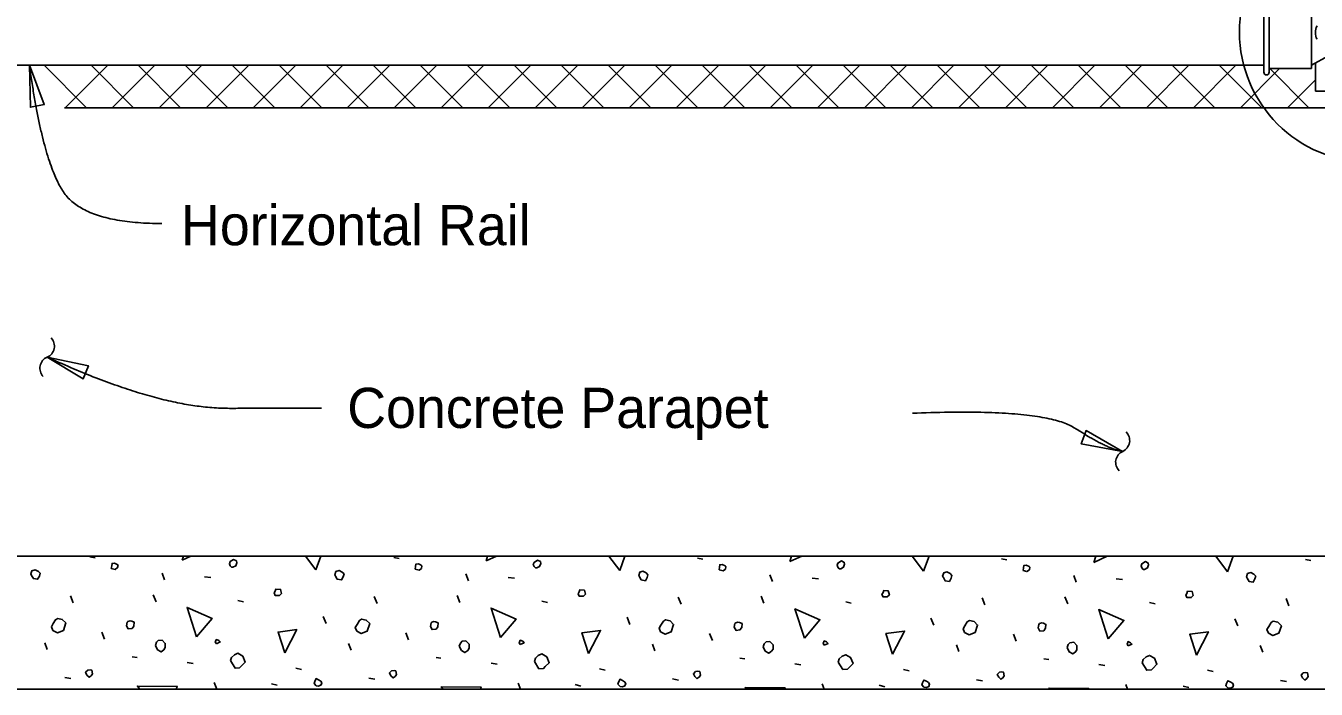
# Model space of a CAD drawing. Extents: x 0 to 41.1, y 0 to 25.9.
# Drawn here: x 5.34 to 11.81, y 14.04 to 17.37 of the extents above; entities that cross this region are included whole.
import ezdxf

# ---------------------------------------------------------------- set-up
doc = ezdxf.new("R2010")
doc.units = 0
for name, color, linetype in [('Dimension', 7, 'Continuous'), ('Miscellaneous', 7, 'Continuous'), ('SteelMisc', 7, 'Continuous'), ('SupstrConc', 7, 'Continuous'), ('TextStructures', 7, 'Continuous')]:
    doc.layers.add(name, color=color, linetype=linetype)

msp = doc.modelspace()

# ---------------------------------------------------------------- linework, layer by layer
at = {"layer": 'Dimension'}
for points in [[(5.3566, 17.1708), (5.3616, 16.9597), (5.4309, 16.9731)], [(5.4456, 15.7069), (5.6265, 15.5979), (5.6523, 15.6635)], [(10.8378, 15.2332), (10.6542, 15.3377), (10.6301, 15.2714)]]:
    msp.add_lwpolyline(points, close=True, dxfattribs=at)
msp.add_circle((12.0765, 17.337), 0.6527, dxfattribs=at)
for centre, start, end in [((5.4222, 15.7609), 292.70915, 44.43637), ((5.4682, 15.651), 112.70915, 224.43637), ((10.8136, 15.2881), 294.14658, 45.87379), ((10.8624, 15.1793), 114.14657, 225.87379)]:
    msp.add_arc(centre, 0.0596, start, end, dxfattribs=at)
for points in [[(6.0197, 16.3768), (5.6218, 16.3768), (5.4178, 16.7138), (5.3566, 17.1707)], [(6.8209, 15.4497), (6.7025, 15.4497), (6.0031, 15.4497), (5.4454, 15.7067)], [(9.7834, 15.4246), (10.44, 15.453), (10.7614, 15.2449), (10.838, 15.2337)]]:
    msp.add_open_spline(points, degree=2, dxfattribs=at)
at = {"layer": 'Miscellaneous'}
for p, q in [((5.6432, 16.9573), (5.4297, 17.1708)), ((5.7493, 17.1708), (5.5358, 16.9573)), ((5.8789, 16.9573), (5.6654, 17.1708)), ((5.985, 17.1708), (5.7715, 16.9573)), ((6.1146, 16.9573), (5.9011, 17.1708)), ((6.2207, 17.1708), (6.0072, 16.9573)), ((6.3503, 16.9573), (6.1368, 17.1708)), ((6.4564, 17.1708), (6.2429, 16.9573)), ((6.586, 16.9573), (6.3725, 17.1708)), ((6.6921, 17.1708), (6.4786, 16.9573)), ((6.8217, 16.9573), (6.6082, 17.1708)), ((6.9278, 17.1708), (6.7143, 16.9573)), ((7.0574, 16.9573), (6.8439, 17.1708)), ((7.1635, 17.1708), (6.95, 16.9573)), ((7.2931, 16.9573), (7.0796, 17.1708)), ((7.3992, 17.1708), (7.1857, 16.9573)), ((7.5288, 16.9573), (7.3153, 17.1708)), ((7.6349, 17.1708), (7.4214, 16.9573)), ((7.7645, 16.9573), (7.551, 17.1708)), ((7.8706, 17.1708), (7.6571, 16.9573)), ((8.0002, 16.9573), (7.7867, 17.1708)), ((8.1063, 17.1708), (7.8928, 16.9573)), ((8.2359, 16.9573), (8.0224, 17.1708)), ((8.342, 17.1708), (8.1285, 16.9573)), ((8.4716, 16.9573), (8.2581, 17.1708)), ((8.5777, 17.1708), (8.3642, 16.9573)), ((8.7073, 16.9573), (8.4938, 17.1708)), ((8.8134, 17.1708), (8.5999, 16.9573)), ((8.943, 16.9573), (8.7295, 17.1708)), ((9.0491, 17.1708), (8.8356, 16.9573)), ((9.1788, 16.9573), (8.9652, 17.1708)), ((9.2848, 17.1708), (9.0713, 16.9573)), ((9.4145, 16.9573), (9.2009, 17.1708)), ((9.5205, 17.1708), (9.307, 16.9573)), ((9.6502, 16.9573), (9.4366, 17.1708)), ((9.7562, 17.1708), (9.5427, 16.9573)), ((9.8859, 16.9573), (9.6723, 17.1708)), ((9.9919, 17.1708), (9.7784, 16.9573)), ((10.1216, 16.9573), (9.908, 17.1708)), ((10.2276, 17.1708), (10.0141, 16.9573)), ((10.3573, 16.9573), (10.1437, 17.1708)), ((10.4633, 17.1708), (10.2498, 16.9573)), ((10.593, 16.9573), (10.3794, 17.1708)), ((10.6991, 17.1708), (10.4855, 16.9573)), ((10.8287, 16.9573), (10.6151, 17.1708)), ((10.9348, 17.1708), (10.7212, 16.9573)), ((11.0644, 16.9573), (10.8508, 17.1708)), ((11.1705, 17.1708), (10.9569, 16.9573)), ((11.3001, 16.9573), (11.0865, 17.1708)), ((11.4062, 17.1708), (11.1926, 16.9573)), ((11.5358, 16.9573), (11.3222, 17.1708)), ((11.6246, 17.1536), (11.4283, 16.9573)), ((11.7715, 16.9573), (11.5752, 17.1536)), ((11.8042, 17.0974), (11.664, 16.9573)), ((5.6591, 14.7053), (5.6856, 14.7)), ((7.1829, 14.7017), (7.2094, 14.6964)), ((8.7067, 14.6982), (8.7332, 14.6929)), ((10.2305, 14.6946), (10.257, 14.6893)), ((11.7543, 14.6911), (11.7808, 14.6858)), ((6.0338, 14.5886), (6.0214, 14.6222)), ((6.2336, 14.6045), (6.2654, 14.601)), ((7.5576, 14.585), (7.5453, 14.6186)), ((7.7574, 14.601), (7.7892, 14.5974)), ((9.0815, 14.5815), (9.0691, 14.6151)), ((9.2812, 14.5974), (9.313, 14.5939)), ((10.6053, 14.578), (10.5929, 14.6116)), ((10.805, 14.5939), (10.8368, 14.5904)), ((5.576, 14.4737), (5.5618, 14.509)), ((5.9914, 14.479), (5.9773, 14.5143)), ((7.0998, 14.4701), (7.0856, 14.5055)), ((7.5152, 14.4754), (7.5011, 14.5108)), ((8.6236, 14.4666), (8.6095, 14.502)), ((9.039, 14.4719), (9.0249, 14.5073)), ((10.1474, 14.4631), (10.1333, 14.4984)), ((10.5628, 14.4684), (10.5487, 14.5037)), ((11.6712, 14.4595), (11.6571, 14.4949)), ((6.4015, 14.4861), (6.4298, 14.479)), ((7.9253, 14.4825), (7.9536, 14.4754)), ((9.4491, 14.479), (9.4774, 14.4719)), ((10.973, 14.4754), (11.0012, 14.4684)), ((6.8435, 14.3694), (6.8293, 14.4047)), ((8.3673, 14.3658), (8.3531, 14.4012)), ((9.8911, 14.3623), (9.8769, 14.3977)), ((11.4149, 14.3588), (11.4008, 14.3941)), ((5.7333, 14.2916), (5.7192, 14.327)), ((7.2571, 14.2881), (7.243, 14.3234)), ((8.7809, 14.2845), (8.7668, 14.3199)), ((10.3047, 14.281), (10.2906, 14.3163)), ((5.4452, 14.2403), (5.4328, 14.2739)), ((6.969, 14.2368), (6.9566, 14.2704)), ((8.4928, 14.2333), (8.4804, 14.2668)), ((10.0166, 14.2297), (10.0042, 14.2633)), ((11.5404, 14.2262), (11.528, 14.2598)), ((5.8712, 14.2032), (5.8959, 14.1997)), ((6.147, 14.1749), (6.177, 14.1696)), ((7.395, 14.1997), (7.4198, 14.1961)), ((7.6708, 14.1714), (7.7008, 14.1661)), ((8.9188, 14.1961), (8.9436, 14.1926)), ((10.4426, 14.1926), (10.4674, 14.1891)), ((6.6914, 14.1466), (6.7197, 14.1396)), ((8.2152, 14.1431), (8.2435, 14.136)), ((9.1946, 14.1679), (9.2246, 14.1626)), ((9.7391, 14.1396), (9.7673, 14.1325)), ((10.7184, 14.1643), (10.7485, 14.159)), ((11.2629, 14.136), (11.2912, 14.129)), ((5.5335, 14.0989), (5.5636, 14.0936)), ((6.2955, 14.0406), (6.2831, 14.0742)), ((6.5695, 14.0671), (6.5977, 14.06)), ((7.0574, 14.0954), (7.0874, 14.0901)), ((7.818, 14.0406), (7.8069, 14.0706)), ((8.0933, 14.0636), (8.1216, 14.0565)), ((8.5812, 14.0918), (8.6112, 14.0865)), ((9.3405, 14.0406), (9.3307, 14.0671)), ((9.6171, 14.06), (9.6454, 14.0529)), ((10.105, 14.0883), (10.135, 14.083)), ((10.863, 14.0406), (10.8545, 14.0636)), ((11.1409, 14.0565), (11.1692, 14.0494)), ((11.6288, 14.0848), (11.6589, 14.0795))]:
    msp.add_line(p, q, dxfattribs=at)
for points in [[(6.1222, 14.6876), (6.1283, 14.7072)], [(6.166, 14.7072), (6.1222, 14.6876)], [(6.3697, 14.6522), (6.3768, 14.6522), (6.3909, 14.6593), (6.3962, 14.6752), (6.3944, 14.684), (6.3803, 14.6911), (6.3626, 14.6805), (6.3591, 14.6699), (6.3626, 14.6593), (6.3697, 14.6522)], [(6.7922, 14.6398), (6.741, 14.7072)], [(6.8174, 14.7072), (6.7922, 14.6398)], [(7.646, 14.684), (7.6532, 14.7072)], [(7.6977, 14.7072), (7.646, 14.684)], [(7.8935, 14.6487), (7.9006, 14.6487), (7.9147, 14.6558), (7.92, 14.6717), (7.9183, 14.6805), (7.9041, 14.6876), (7.8864, 14.677), (7.8829, 14.6664), (7.8864, 14.6558), (7.8935, 14.6487)], [(8.316, 14.6363), (8.2621, 14.7072)], [(8.3425, 14.7072), (8.316, 14.6363)], [(9.1698, 14.6805), (9.1781, 14.7072)], [(9.2293, 14.7072), (9.1698, 14.6805)], [(9.8398, 14.6328), (9.7832, 14.7072)], [(9.8677, 14.7072), (9.8398, 14.6328)], [(10.6937, 14.677), (10.703, 14.7072)], [(10.761, 14.7072), (10.6937, 14.677)], [(11.3636, 14.6292), (11.3044, 14.7072)], [(11.3928, 14.7072), (11.3636, 14.6292)], [(5.3674, 14.6116), (5.3762, 14.5957), (5.3974, 14.5921), (5.4063, 14.608), (5.4098, 14.6222), (5.401, 14.631), (5.3851, 14.6398), (5.3691, 14.6345), (5.3638, 14.6186), (5.3674, 14.6116)], [(5.7669, 14.6469), (5.7863, 14.6416), (5.7987, 14.6505), (5.8005, 14.6628), (5.7969, 14.6664), (5.7828, 14.6734), (5.7704, 14.6717), (5.7687, 14.6593), (5.7669, 14.6469)], [(6.8912, 14.608), (6.9, 14.5921), (6.9212, 14.5886), (6.9301, 14.6045), (6.9336, 14.6186), (6.9248, 14.6275), (6.9089, 14.6363), (6.893, 14.631), (6.8877, 14.6151), (6.8912, 14.608)], [(7.2907, 14.6434), (7.3101, 14.6381), (7.3225, 14.6469), (7.3243, 14.6593), (7.3208, 14.6628), (7.3066, 14.6699), (7.2942, 14.6681), (7.2925, 14.6558), (7.2907, 14.6434)], [(8.415, 14.6045), (8.4238, 14.5886), (8.4451, 14.585), (8.4539, 14.601), (8.4574, 14.6151), (8.4486, 14.6239), (8.4327, 14.6328), (8.4168, 14.6275), (8.4115, 14.6116), (8.415, 14.6045)], [(8.8145, 14.6398), (8.834, 14.6345), (8.8463, 14.6434), (8.8481, 14.6558), (8.8446, 14.6593), (8.8304, 14.6664), (8.8181, 14.6646), (8.8163, 14.6522), (8.8145, 14.6398)], [(9.4173, 14.6452), (9.4244, 14.6452), (9.4385, 14.6522), (9.4438, 14.6681), (9.4421, 14.677), (9.4279, 14.684), (9.4103, 14.6734), (9.4067, 14.6628), (9.4103, 14.6522), (9.4173, 14.6452)], [(9.9388, 14.601), (9.9477, 14.585), (9.9689, 14.5815), (9.9777, 14.5974), (9.9812, 14.6116), (9.9724, 14.6204), (9.9565, 14.6292), (9.9406, 14.6239), (9.9353, 14.608), (9.9388, 14.601)], [(10.3383, 14.6363), (10.3578, 14.631), (10.3702, 14.6398), (10.3719, 14.6522), (10.3684, 14.6558), (10.3542, 14.6628), (10.3419, 14.6611), (10.3401, 14.6487), (10.3383, 14.6363)], [(10.9411, 14.6416), (10.9482, 14.6416), (10.9624, 14.6487), (10.9677, 14.6646), (10.9659, 14.6734), (10.9517, 14.6805), (10.9341, 14.6699), (10.9305, 14.6593), (10.9341, 14.6487), (10.9411, 14.6416)], [(11.4626, 14.5974), (11.4715, 14.5815), (11.4927, 14.578), (11.5015, 14.5939), (11.5051, 14.608), (11.4962, 14.6169), (11.4803, 14.6257), (11.4644, 14.6204), (11.4591, 14.6045), (11.4626, 14.5974)], [(6.5889, 14.5108), (6.6101, 14.5108), (6.6207, 14.5214), (6.6154, 14.5409), (6.5924, 14.5426), (6.5889, 14.532), (6.5836, 14.5232), (6.5889, 14.5108), (6.5854, 14.5143)], [(8.1127, 14.5073), (8.1339, 14.5073), (8.1445, 14.5179), (8.1392, 14.5373), (8.1163, 14.5391), (8.1127, 14.5285), (8.1074, 14.5196), (8.1127, 14.5073), (8.1092, 14.5108)], [(9.6365, 14.5037), (9.6577, 14.5037), (9.6684, 14.5143), (9.663, 14.5338), (9.6401, 14.5355), (9.6365, 14.5249), (9.6312, 14.5161), (9.6365, 14.5037), (9.633, 14.5073)], [(11.1603, 14.5002), (11.1816, 14.5002), (11.1922, 14.5108), (11.1869, 14.5302), (11.1639, 14.532), (11.1603, 14.5214), (11.155, 14.5126), (11.1603, 14.5002), (11.1568, 14.5037)], [(6.1947, 14.304), (6.147, 14.4507), (6.2725, 14.3959), (6.1947, 14.304)], [(7.7185, 14.3004), (7.6708, 14.4472), (7.7963, 14.3924), (7.7185, 14.3004)], [(9.2423, 14.2969), (9.1946, 14.4436), (9.3201, 14.3888), (9.2423, 14.2969)], [(10.7661, 14.2934), (10.7184, 14.4401), (10.8439, 14.3853), (10.7661, 14.2934)], [(5.4734, 14.3358), (5.4964, 14.3234), (5.5265, 14.3358), (5.5388, 14.3729), (5.5212, 14.3906), (5.4982, 14.3959), (5.4876, 14.3888), (5.4752, 14.3694), (5.4664, 14.3535), (5.4734, 14.3358)], [(5.8429, 14.3588), (5.8517, 14.3429), (5.8712, 14.3446), (5.88, 14.357), (5.8818, 14.3765), (5.8694, 14.3818), (5.8606, 14.3835), (5.85, 14.38), (5.8464, 14.3765), (5.8429, 14.3588)], [(6.9973, 14.3323), (7.0202, 14.3199), (7.0503, 14.3323), (7.0627, 14.3694), (7.045, 14.3871), (7.022, 14.3924), (7.0114, 14.3853), (6.999, 14.3658), (6.9902, 14.3499), (6.9973, 14.3323)], [(7.3667, 14.3552), (7.3756, 14.3393), (7.395, 14.3411), (7.4038, 14.3535), (7.4056, 14.3729), (7.3932, 14.3782), (7.3844, 14.38), (7.3738, 14.3765), (7.3703, 14.3729), (7.3667, 14.3552)], [(8.5211, 14.3287), (8.5441, 14.3163), (8.5741, 14.3287), (8.5865, 14.3658), (8.5688, 14.3835), (8.5458, 14.3888), (8.5352, 14.3818), (8.5228, 14.3623), (8.514, 14.3464), (8.5211, 14.3287)], [(8.8905, 14.3517), (8.8994, 14.3358), (8.9188, 14.3376), (8.9277, 14.3499), (8.9294, 14.3694), (8.917, 14.3747), (8.9082, 14.3765), (8.8976, 14.3729), (8.8941, 14.3694), (8.8905, 14.3517)], [(10.0449, 14.3252), (10.0679, 14.3128), (10.0979, 14.3252), (10.1103, 14.3623), (10.0926, 14.38), (10.0696, 14.3853), (10.059, 14.3782), (10.0467, 14.3588), (10.0378, 14.3429), (10.0449, 14.3252)], [(10.4143, 14.3482), (10.4232, 14.3323), (10.4426, 14.334), (10.4515, 14.3464), (10.4532, 14.3658), (10.4409, 14.3711), (10.432, 14.3729), (10.4214, 14.3694), (10.4179, 14.3658), (10.4143, 14.3482)], [(11.5687, 14.3216), (11.5917, 14.3093), (11.6217, 14.3216), (11.6341, 14.3588), (11.6164, 14.3765), (11.5934, 14.3818), (11.5828, 14.3747), (11.5705, 14.3552), (11.5616, 14.3393), (11.5687, 14.3216)], [(6.6366, 14.2227), (6.603, 14.327), (6.6967, 14.3393), (6.6366, 14.2227)], [(8.1604, 14.2191), (8.1269, 14.3234), (8.2205, 14.3358), (8.1604, 14.2191)], [(9.6843, 14.2156), (9.6507, 14.3199), (9.7444, 14.3323), (9.6843, 14.2156)], [(11.2081, 14.212), (11.1745, 14.3163), (11.2682, 14.3287), (11.2081, 14.212)], [(5.9879, 14.2598), (5.9985, 14.2386), (6.0161, 14.228), (6.0303, 14.2386), (6.0374, 14.2492), (6.0374, 14.2704), (6.0214, 14.2863), (6.002, 14.2845), (5.9932, 14.2757), (5.9879, 14.2598)], [(6.2937, 14.2686), (6.3131, 14.2775), (6.3061, 14.2845), (6.2937, 14.2898), (6.2884, 14.2775), (6.2937, 14.2686)], [(7.5117, 14.2562), (7.5223, 14.235), (7.54, 14.2244), (7.5541, 14.235), (7.5612, 14.2456), (7.5612, 14.2668), (7.5453, 14.2828), (7.5258, 14.281), (7.517, 14.2722), (7.5117, 14.2562)], [(7.8175, 14.2651), (7.8369, 14.2739), (7.8299, 14.281), (7.8175, 14.2863), (7.8122, 14.2739), (7.8175, 14.2651)], [(9.0355, 14.2527), (9.0461, 14.2315), (9.0638, 14.2209), (9.0779, 14.2315), (9.085, 14.2421), (9.085, 14.2633), (9.0691, 14.2792), (9.0496, 14.2775), (9.0408, 14.2686), (9.0355, 14.2527)], [(9.3413, 14.2615), (9.3608, 14.2704), (9.3537, 14.2775), (9.3413, 14.2828), (9.336, 14.2704), (9.3413, 14.2615)], [(10.5593, 14.2492), (10.5699, 14.228), (10.5876, 14.2174), (10.6017, 14.228), (10.6088, 14.2386), (10.6088, 14.2598), (10.5929, 14.2757), (10.5734, 14.2739), (10.5646, 14.2651), (10.5593, 14.2492)], [(10.8651, 14.258), (10.8846, 14.2668), (10.8775, 14.2739), (10.8651, 14.2792), (10.8598, 14.2668), (10.8651, 14.258)], [(6.3644, 14.1838), (6.3874, 14.1466), (6.4104, 14.1484), (6.4192, 14.1572), (6.4386, 14.1767), (6.4263, 14.2067), (6.4015, 14.2209), (6.3838, 14.2138), (6.3697, 14.1997), (6.3644, 14.1838)], [(7.8882, 14.1802), (7.9112, 14.1431), (7.9342, 14.1449), (7.943, 14.1537), (7.9625, 14.1732), (7.9501, 14.2032), (7.9253, 14.2174), (7.9077, 14.2103), (7.8935, 14.1961), (7.8882, 14.1802)], [(9.412, 14.1767), (9.435, 14.1396), (9.458, 14.1413), (9.4668, 14.1502), (9.4863, 14.1696), (9.4739, 14.1997), (9.4491, 14.2138), (9.4315, 14.2067), (9.4173, 14.1926), (9.412, 14.1767)], [(10.9358, 14.1732), (10.9588, 14.136), (10.9818, 14.1378), (10.9906, 14.1466), (11.0101, 14.1661), (10.9977, 14.1961), (10.973, 14.2103), (10.9553, 14.2032), (10.9411, 14.1891), (10.9358, 14.1732)], [(5.6449, 14.1113), (5.6555, 14.1007), (5.6661, 14.1077), (5.6732, 14.1184), (5.6697, 14.136), (5.6608, 14.1378), (5.6484, 14.136), (5.6378, 14.1254), (5.6449, 14.1113)], [(7.1687, 14.1077), (7.1793, 14.0971), (7.1899, 14.1042), (7.197, 14.1148), (7.1935, 14.1325), (7.1846, 14.1343), (7.1723, 14.1325), (7.1617, 14.1219), (7.1687, 14.1077)], [(8.6925, 14.1042), (8.7031, 14.0936), (8.7138, 14.1007), (8.7208, 14.1113), (8.7173, 14.129), (8.7085, 14.1307), (8.6961, 14.129), (8.6855, 14.1184), (8.6925, 14.1042)], [(10.2164, 14.1007), (10.227, 14.0901), (10.2376, 14.0971), (10.2446, 14.1077), (10.2411, 14.1254), (10.2323, 14.1272), (10.2199, 14.1254), (10.2093, 14.1148), (10.2164, 14.1007)], [(11.7402, 14.0971), (11.7508, 14.0865), (11.7614, 14.0936), (11.7685, 14.1042), (11.7649, 14.1219), (11.7561, 14.1237), (11.7437, 14.1219), (11.7331, 14.1113), (11.7402, 14.0971)], [(5.9098, 14.0406), (5.8977, 14.0565), (6.0975, 14.0547), (6.0922, 14.0406)], [(6.794, 14.0583), (6.8063, 14.0565), (6.8187, 14.0618), (6.8222, 14.0724), (6.8169, 14.0812), (6.8063, 14.0883), (6.794, 14.0936), (6.7869, 14.0795), (6.7834, 14.0689), (6.794, 14.0583)], [(7.4309, 14.0406), (7.4215, 14.0529), (7.6213, 14.0512), (7.6173, 14.0406)], [(8.3178, 14.0547), (8.3302, 14.0529), (8.3425, 14.0583), (8.3461, 14.0689), (8.3408, 14.0777), (8.3302, 14.0848), (8.3178, 14.0901), (8.3107, 14.0759), (8.3072, 14.0653), (8.3178, 14.0547)], [(8.9521, 14.0406), (8.9453, 14.0494), (9.1451, 14.0476), (9.1424, 14.0406)], [(9.8416, 14.0512), (9.854, 14.0494), (9.8663, 14.0547), (9.8699, 14.0653), (9.8646, 14.0742), (9.854, 14.0812), (9.8416, 14.0865), (9.8345, 14.0724), (9.831, 14.0618), (9.8416, 14.0512)], [(10.4732, 14.0406), (10.4691, 14.0459), (10.6689, 14.0441), (10.6676, 14.0406)], [(11.3654, 14.0476), (11.3778, 14.0459), (11.3902, 14.0512), (11.3937, 14.0618), (11.3884, 14.0706), (11.3778, 14.0777), (11.3654, 14.083), (11.3583, 14.0689), (11.3548, 14.0583), (11.3654, 14.0476)]]:
    msp.add_lwpolyline(points, dxfattribs=at)
at = {"layer": 'SteelMisc'}
for p, q in [((11.5457, 17.4454), (11.5457, 17.1357)), ((11.5725, 17.4454), (11.5725, 17.1357)), ((11.7855, 17.4258), (11.7855, 17.1536)), ((11.7855, 17.1717), (11.9994, 17.2902)), ((11.5457, 17.1708), (2.6043, 17.1708)), ((11.5725, 17.1536), (11.7855, 17.1536)), ((11.8042, 17.0406), (11.8042, 17.182)), ((11.8667, 17.0406), (11.8042, 17.0406))]:
    msp.add_line(p, q, dxfattribs=at)
msp.add_arc((11.5592, 17.1355), 0.0134, 180, 0, dxfattribs=at)
msp.add_ellipse((11.8818, 17.3345), major_axis=(-0.0776, 0), ratio=0.957868, start_param=5.810211, end_param=6.75616, dxfattribs=at)
at = {"layer": 'SupstrConc'}
for p, q in [((5.5315, 16.9573), (18.6893, 16.9573)), ((0.6881, 14.7072), (23.462, 14.7072)), ((0.6881, 14.0406), (23.462, 14.0406))]:
    msp.add_line(p, q, dxfattribs=at)

# ---------------------------------------------------------------- texts
at = {"layer": 'TextStructures'}
for s, p in [('Horizontal Rail', (6.1165, 16.2676)), ('Concrete Parapet', (6.9497, 15.351))]:
    msp.add_text(s, height=0.2016, dxfattribs=at).set_placement(p)

doc.saveas('drawing.dxf')
